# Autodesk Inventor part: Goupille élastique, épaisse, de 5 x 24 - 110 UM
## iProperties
Shininess: 20.0
Angle Display Precision: 2
Document Length Units: 11269
Document Angle Units: 11279
Document Time Units: 11290
Document Mass Units: 11283
Document Length Units Precision: 3
Document Angle Units Precision: 2
Created: 2002-02
Part Number: Goupille élastique, épaisse, de 5 x 24 - 110 UM
Material: Par défaut
Catalog Web Link: www.traceparts.com
Description: Goupille élastique, épaisse, de 5 x 24 - UNI 6874
Document SubType Name: Modélisation
Designer: Administrateur
Density: 0.0
Volumn: 0.0
Area: 0.0
PropertySet Name: Model Information
Control State: 0
Master: False
Checked Out: False
Author: Administrateur
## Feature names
1. Base1
